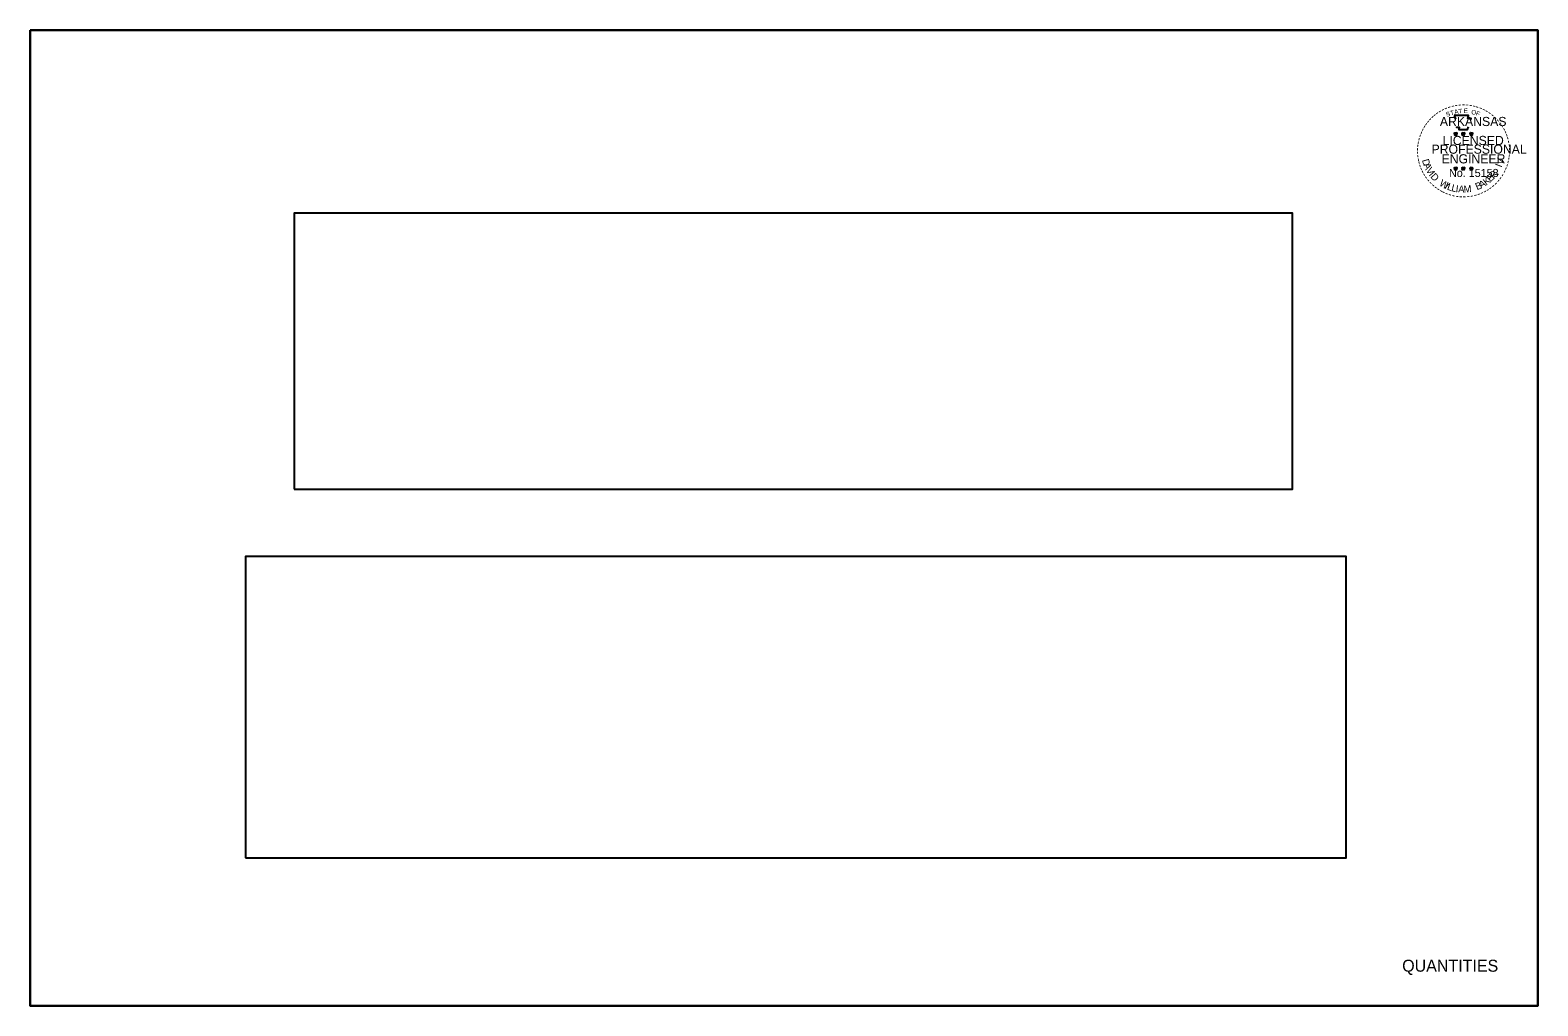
# Model space of a CAD drawing. Extents: x 31847 to 33828, y 52928 to 59118.
# Drawn here: x 31847 to 33547, y 58018 to 59118 of the extents above; entities that cross this region are included whole.
import ezdxf

# ---------------------------------------------------------------- set-up
doc = ezdxf.new("R2010")
doc.units = 0
for name, color, linetype in [('Default', 7, 'Continuous'), ('DSN_DRFT_Junk-No-Plot', 7, 'Continuous'), ('R_Border Notes', 7, 'Continuous'), ('R_Border PE', 7, 'Continuous')]:
    doc.layers.add(name, color=color, linetype=linetype)

msp = doc.modelspace()

# ---------------------------------------------------------------- linework, layer by layer
at = {"layer": 'Default'}
for points in [[(31846.8, 59118), (31846.8, 58018), (33546.8, 58018), (33546.8, 59118)], [(32144.4, 58600.5), (33270.3, 58600.5), (33270.3, 58911.6), (32144.4, 58911.6)], [(32089.4, 58185), (33330.8, 58185), (33330.8, 58524.6), (32089.4, 58524.6)]]:
    msp.add_lwpolyline(points, close=True, dxfattribs=at)
at = {"layer": 'DSN_DRFT_Junk-No-Plot'}
msp.add_lwpolyline([(31846.8, 59118), (33546.8, 59118), (33546.8, 58018), (31846.8, 58018)], close=True, dxfattribs=at)
at = {"layer": 'R_Border PE'}
for p, q in [((33452.3, 59001.7), (33454.1, 59001.2)), ((33452.3, 59001.7), (33453.6, 59001.5)), ((33452.3, 59001.7), (33453.6, 59001.1)), ((33453, 58999.6), (33454.1, 59001.2)), ((33453, 58999.6), (33453.7, 59000.9)), ((33453, 58999.6), (33454.1, 59000.7)), ((33454.1, 59003), (33453.9, 59001.7)), ((33454.1, 59001.2), (33454.1, 59003)), ((33454.1, 59003), (33454.4, 59001.7)), ((33455.9, 59001.7), (33454.1, 59001.2)), ((33455.2, 58999.6), (33454.1, 59001.2)), ((33455.2, 58999.6), (33454.1, 59000.7)), ((33455.9, 59001.7), (33454.4, 59001.5)), ((33455.2, 58999.6), (33454.5, 59001.1)), ((33455.9, 59001.7), (33454.9, 59001.2)), ((33460.9, 59001.7), (33462.7, 59001.2)), ((33460.9, 59001.7), (33462.2, 59001.5)), ((33460.9, 59001.7), (33462.2, 59001.1)), ((33461.6, 58999.6), (33462.7, 59001.2)), ((33461.6, 58999.6), (33462.3, 59000.9)), ((33461.6, 58999.6), (33462.7, 59000.7)), ((33462.7, 59003), (33462.5, 59001.7)), ((33462.7, 59001.2), (33462.7, 59003)), ((33462.7, 59003), (33463, 59001.7)), ((33464.5, 59001.7), (33462.7, 59001.2)), ((33463.8, 58999.6), (33462.7, 59001.2)), ((33463.8, 58999.6), (33462.7, 59000.7)), ((33464.5, 59001.7), (33463.1, 59001.5)), ((33463.8, 58999.6), (33463.1, 59001.1)), ((33464.5, 59001.7), (33463.5, 59001.2)), ((33470, 59001.7), (33471.8, 59001.1)), ((33470, 59001.7), (33471.3, 59001.4)), ((33470, 59001.7), (33471.3, 59001)), ((33470.7, 58999.6), (33471.8, 59001.1)), ((33470.7, 58999.6), (33471.4, 59000.8)), ((33470.7, 58999.6), (33471.8, 59000.7)), ((33471.8, 59003), (33471.6, 59001.7)), ((33471.8, 59001.1), (33471.8, 59003)), ((33471.8, 59003), (33472.1, 59001.7)), ((33473.6, 59001.7), (33471.8, 59001.1)), ((33472.9, 58999.6), (33471.8, 59001.1)), ((33472.9, 58999.6), (33471.8, 59000.7)), ((33473.6, 59001.7), (33472.2, 59001.4)), ((33472.9, 58999.6), (33472.2, 59001.1)), ((33473.6, 59001.7), (33472.6, 59001.1)), ((33452.3, 58962.7), (33454.1, 58962.1)), ((33452.3, 58962.7), (33453.6, 58962.4)), ((33452.3, 58962.7), (33453.5, 58962.1)), ((33453, 58960.6), (33454.1, 58962.1)), ((33453, 58960.6), (33453.6, 58961.8)), ((33453, 58960.6), (33454.1, 58961.7)), ((33454.1, 58964), (33453.9, 58962.7)), ((33454.1, 58962.1), (33454.1, 58964)), ((33454.1, 58964), (33454.4, 58962.7)), ((33455.9, 58962.7), (33454.1, 58962.1)), ((33455.2, 58960.6), (33454.1, 58962.1)), ((33455.2, 58960.6), (33454.1, 58961.7)), ((33455.9, 58962.7), (33454.4, 58962.4)), ((33455.2, 58960.6), (33454.5, 58962.1)), ((33455.9, 58962.7), (33454.8, 58962.2)), ((33460.9, 58962.7), (33462.7, 58962.1)), ((33460.9, 58962.7), (33462.2, 58962.4)), ((33460.9, 58962.7), (33462.1, 58962.1)), ((33461.6, 58960.6), (33462.7, 58962.1)), ((33461.6, 58960.6), (33462.3, 58961.8)), ((33461.6, 58960.6), (33462.7, 58961.7)), ((33462.7, 58964), (33462.5, 58962.7)), ((33462.7, 58962.1), (33462.7, 58964)), ((33462.7, 58964), (33463, 58962.7)), ((33464.5, 58962.7), (33462.7, 58962.1)), ((33463.8, 58960.6), (33462.7, 58962.1)), ((33463.8, 58960.6), (33462.7, 58961.7)), ((33464.5, 58962.7), (33463, 58962.4)), ((33463.8, 58960.6), (33463.1, 58962.1)), ((33464.5, 58962.7), (33463.5, 58962.2)), ((33470, 58962.6), (33471.8, 58962.1)), ((33470, 58962.6), (33471.3, 58962.4)), ((33470, 58962.6), (33471.3, 58962)), ((33470.7, 58960.5), (33471.8, 58962.1)), ((33470.7, 58960.5), (33471.4, 58961.8)), ((33470.7, 58960.5), (33471.8, 58961.6)), ((33471.8, 58963.9), (33471.6, 58962.6)), ((33471.8, 58962.1), (33471.8, 58963.9)), ((33471.8, 58963.9), (33472.1, 58962.7)), ((33473.6, 58962.6), (33471.8, 58962.1)), ((33472.9, 58960.5), (33471.8, 58962.1)), ((33472.9, 58960.5), (33471.8, 58961.6)), ((33473.6, 58962.6), (33472.1, 58962.4)), ((33472.9, 58960.5), (33472.2, 58962)), ((33473.6, 58962.6), (33472.6, 58962.1))]:
    msp.add_line(p, q, dxfattribs=at)
for points in [[(33452.5, 59021.7), (33453.9, 59017.5)], [(33470.6, 59017), (33471.4, 59018.4), (33467.8, 59018.3), (33468.6, 59021.7), (33452.5, 59021.7)], [(33455.1, 59009.2), (33455.1, 59008.8), (33458, 59008.7), (33457.7, 59006.2), (33467.3, 59006.2), (33468.4, 59009)], [(33454.1, 59003), (33455.2, 58999.6), (33452.3, 59001.7), (33455.9, 59001.7), (33453, 58999.6), (33454.1, 59003)], [(33462.7, 59003), (33463.8, 58999.6), (33460.9, 59001.7), (33464.5, 59001.7), (33461.6, 58999.6), (33462.7, 59003)], [(33471.8, 59003), (33472.9, 58999.6), (33470, 59001.7), (33473.6, 59001.7), (33470.7, 58999.6), (33471.8, 59003)], [(33454.1, 58964), (33455.2, 58960.6), (33452.3, 58962.7), (33455.9, 58962.7), (33453, 58960.6), (33454.1, 58964)], [(33462.7, 58964), (33463.8, 58960.6), (33460.9, 58962.7), (33464.5, 58962.7), (33461.6, 58960.6), (33462.7, 58964)], [(33471.8, 58963.9), (33472.9, 58960.5), (33470, 58962.6), (33473.6, 58962.6), (33470.7, 58960.5), (33471.8, 58963.9)]]:
    msp.add_lwpolyline(points, dxfattribs=at)
for centre, radius in [((33454.1, 59001.2), 0.888), ((33454.1, 59001.2), 0.745), ((33454.1, 59001.2), 0.597), ((33454.1, 59001.2), 0.511), ((33454.1, 59001.2), 0.385), ((33454.1, 59001.2), 0.255), ((33454.1, 59001.2), 0.153), ((33462.7, 59001.2), 0.888), ((33462.7, 59001.2), 0.745), ((33462.7, 59001.2), 0.597), ((33462.7, 59001.2), 0.511), ((33462.7, 59001.2), 0.385), ((33462.7, 59001.2), 0.255), ((33462.7, 59001.2), 0.153), ((33471.8, 59001.1), 0.888), ((33471.8, 59001.1), 0.745), ((33471.8, 59001.1), 0.597), ((33471.8, 59001.1), 0.511), ((33471.8, 59001.1), 0.385), ((33471.8, 59001.1), 0.255), ((33471.8, 59001.1), 0.153), ((33454.1, 58962.1), 0.888), ((33454.1, 58962.1), 0.745), ((33454.1, 58962.1), 0.597), ((33454.1, 58962.1), 0.511), ((33454.1, 58962.1), 0.385), ((33454.1, 58962.1), 0.255), ((33454.1, 58962.1), 0.153), ((33462.7, 58962.1), 0.888), ((33462.7, 58962.1), 0.745), ((33462.7, 58962.1), 0.597), ((33462.7, 58962.1), 0.511), ((33462.7, 58962.1), 0.385), ((33462.7, 58962.1), 0.255), ((33462.7, 58962.1), 0.153), ((33471.8, 58962.1), 0.888), ((33471.8, 58962.1), 0.745), ((33471.8, 58962.1), 0.597), ((33471.8, 58962.1), 0.511), ((33471.8, 58962.1), 0.385), ((33471.8, 58962.1), 0.255), ((33471.8, 58962.1), 0.153)]:
    msp.add_circle(centre, radius, dxfattribs=at)

# ---------------------------------------------------------------- texts
at = {"layer": 'R_Border Notes'}
msp.add_text('QUANTITIES', height=13.5, dxfattribs=at).set_placement((33393.8, 58056.5))
at = {"layer": 'R_Border PE'}
for s, height, rotation, p in [('-', 8.25, 36.2317, (33433.5, 59020.6)), ('-', 8.25, 34.0636, (33436.5, 59022.6)), ('-', 8.25, 28.7918, (33439.6, 59024.5)), ('-', 8.25, 24.3072, (33442.8, 59026.1)), ('S', 5.16, 21.594, (33444.1, 59020.1)), ('-', 8.25, 19.1761, (33446.1, 59027.5)), ('T', 5.16, 16.4036, (33448.8, 59021.8)), ('-', 8.25, 13.6302, (33450, 59028.8)), ('A', 5.16, 11.2132, (33453, 59023.1)), ('-', 8.25, 10.2193, (33453.5, 59029.6)), ('T', 5.16, 6.0228, (33457.4, 59023.9)), ('-', 8.25, 5.8968, (33457.2, 59030.2)), ('-', 8.25, 0.1862, (33461.2, 59030.6)), ('E', 5.16, 0.8323, (33463.1, 59024.5)), ('-', 8.25, 357.743, (33464.9, 59030.5)), ('-', 8.25, 352.1617, (33468.8, 59030.2)), ('O', 5.16, 350.4515, (33471.4, 59023.4)), ('-', 8.25, 347.2049, (33472.5, 59029.6)), ('F', 5.16, 340.0707, (33476.3, 59022.2)), ('-', 8.25, 342.3362, (33475.7, 59028.8)), ('-', 8.25, 337.8551, (33479.5, 59027.7)), ('-', 8.25, 334.1211, (33482.8, 59026.3)), ('-', 8.25, 329.6409, (33485.8, 59024.8)), ('-', 8.25, 325.8627, (33489.1, 59022.9)), ('-', 8.25, 62.8713, (33419, 59002.7)), ('-', 8.25, 58.0706, (33420.6, 59005.9)), ('-', 8.25, 54.2325, (33422.3, 59008.6)), ('-', 8.25, 50.6142, (33424.4, 59011.5)), ('-', 8.25, 48.4231, (33426.5, 59014)), ('-', 8.25, 42.9622, (33428.8, 59016.5)), ('-', 8.25, 38.9507, (33431, 59018.6)), ('-', 8.25, 320.5297, (33492.2, 59020.7)), ('-', 8.25, 315.5786, (33495.3, 59018.2)), ('-', 8.25, 309.8797, (33498.2, 59015.4)), ('-', 8.25, 306.6522, (33501, 59012.3)), ('-', 7.22, 303.6753, (33503.5, 59009.4)), ('-', 8.25, 299.6684, (33505.1, 59006.2)), ('-', 8.25, 81.2013, (33414.8, 58988.9)), ('-', 8.25, 75.461, (33415.5, 58992.6)), ('-', 8.25, 72.3945, (33416.5, 58996.3)), ('-', 8.25, 67.7743, (33417.7, 58999.5)), ('-', 8.25, 294.6628, (33506.8, 59003.1)), ('-', 8.25, 290.5728, (33508.1, 59000.1)), ('-', 8.25, 285.1233, (33509.3, 58997.1)), ('-', 8.25, 280.5493, (33510.3, 58993.3)), ('-', 8.25, 94.1959, (33414.5, 58978)), ('-', 8.25, 89.0622, (33414.3, 58981.8)), ('-', 8.25, 85.1863, (33414.4, 58985.4)), ('-', 8.25, 98.9479, (33414.9, 58974.6)), ('-', 8.25, 101.7149, (33415.6, 58970.8)), ('V', 7.94, 72.6573, (33506.7, 58965.5)), ('-', 8.25, 260.9953, (33511.2, 58975.5)), ('-', 8.25, 276.5962, (33511.2, 58989.3)), ('-', 8.25, 263.5172, (33511.6, 58978.9)), ('-', 8.25, 274.3301, (33511.5, 58985.6)), ('-', 8.25, 269.9407, (33511.7, 58982.3)), ('-', 8.25, 105.4578, (33416.4, 58967.7)), ('-', 8.25, 109.0874, (33417.5, 58964.5)), ('-', 8.25, 114.0643, (33418.8, 58961.4)), ('-', 8.25, 115.7289, (33420.4, 58958.2)), ('D', 7.94, 286.2848, (33416, 58971.5)), ('A', 7.94, 292.7835, (33417.5, 58966.3)), ('-', 8.25, 120.4471, (33422.2, 58955.2)), ('V', 7.94, 300.7936, (33420.2, 58960.3)), ('I', 7.94, 308.3502, (33423.4, 58954.9)), ('D', 7.94, 311.9774, (33425.2, 58952.5)), ('E', 7.94, 44.0175, (33493.3, 58946.3)), ('R', 7.94, 50.3651, (33497.1, 58949.9)), ('I', 7.94, 69.0301, (33505.6, 58962.8)), (',', 7.94, 57.4684, (33500.8, 58954.5)), ('-', 8.25, 244.6197, (33507.2, 58961.6)), ('-', 8.25, 247.8887, (33508.5, 58964.9)), ('-', 8.25, 252.8681, (33509.7, 58968.3)), ('-', 8.25, 255.7626, (33510.6, 58972)), ('-', 8.25, 125.8934, (33424.3, 58952.3)), ('-', 8.25, 130.7181, (33426.7, 58949.5)), ('-', 8.25, 134.2238, (33429.4, 58946.7)), ('-', 8.25, 138.9338, (33432.1, 58944.3)), ('-', 8.25, 144.6463, (33434.9, 58942.2)), ('-', 8.25, 148.0898, (33437.8, 58940.3)), ('W', 7.94, 328.0731, (33434.9, 58943.4)), ('I', 7.94, 336.6877, (33441.1, 58939.8)), ('L', 7.94, 340.3149, (33443.8, 58938.5)), ('L', 7.94, 346.6625, (33448.7, 58936.7)), ('I', 7.94, 353.0101, (33453.8, 58935.5)), ('A', 7.94, 356.6373, (33456.8, 58935.1)), ('M', 7.94, 4.6473, (33463.4, 58934.8)), ('B', 7.94, 22.8589, (33478.2, 58937.5)), ('A', 7.94, 28.9042, (33482.8, 58939.4)), ('K', 7.94, 36.9143, (33488.6, 58942.7)), ('-', 8.25, 215.7363, (33492.9, 58943.5)), ('-', 8.25, 221.0851, (33495.7, 58945.9)), ('-', 8.25, 225.7653, (33498.4, 58948.5)), ('-', 8.25, 231.2538, (33500.9, 58951.5)), ('-', 8.25, 233.8452, (33503.1, 58954.4)), ('-', 8.25, 239.0712, (33505.2, 58957.7)), ('-', 8.25, 151.5704, (33440.8, 58938.6)), ('-', 8.25, 154.6002, (33443.5, 58937.3)), ('-', 8.25, 158.5612, (33446.7, 58936)), ('-', 8.25, 162.7983, (33450.3, 58934.9)), ('-', 8.25, 167.5555, (33454, 58934)), ('-', 8.25, 173.1155, (33457.9, 58933.5)), ('-', 8.25, 176.5183, (33461.8, 58933.2)), ('-', 8.25, 181.5918, (33465.6, 58933.3)), ('-', 8.25, 185.8167, (33469.8, 58933.7)), ('-', 8.25, 191.2858, (33473.6, 58934.4)), ('-', 8.25, 195.4743, (33477.4, 58935.4)), ('-', 8.25, 199.4643, (33480.8, 58936.6)), ('-', 8.25, 204.2516, (33484, 58938.1)), ('-', 8.25, 207.3568, (33487.3, 58939.7)), ('-', 8.25, 212.2491, (33490.1, 58941.5))]:
    msp.add_text(s, height=height, rotation=rotation, dxfattribs=at).set_placement(p)
for s, height, p in [('ARKANSAS', 10.31, (33436.3, 59009.9)), ('LICENSED', 10.31, (33439.4, 58988.5)), ('PROFESSIONAL', 10.312, (33426.9, 58978.7)), ('ENGINEER', 10.31, (33438.2, 58967.8)), ('No. 15158', 9.06, (33446.6, 58952.5)), ('AAMU', 0.000103, (33462.4, 58934.7))]:
    msp.add_text(s, height=height, dxfattribs=at).set_placement(p)

doc.saveas('drawing.dxf')
